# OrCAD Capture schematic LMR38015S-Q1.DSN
size D; title: LMR38015S-Q1: LMR38015 SIMPLE SWITCHER®; rev: 1.0; note: Datasheet: SNVSCH7                  EVM: SNVU847; note: Synchronous Step Down Converter
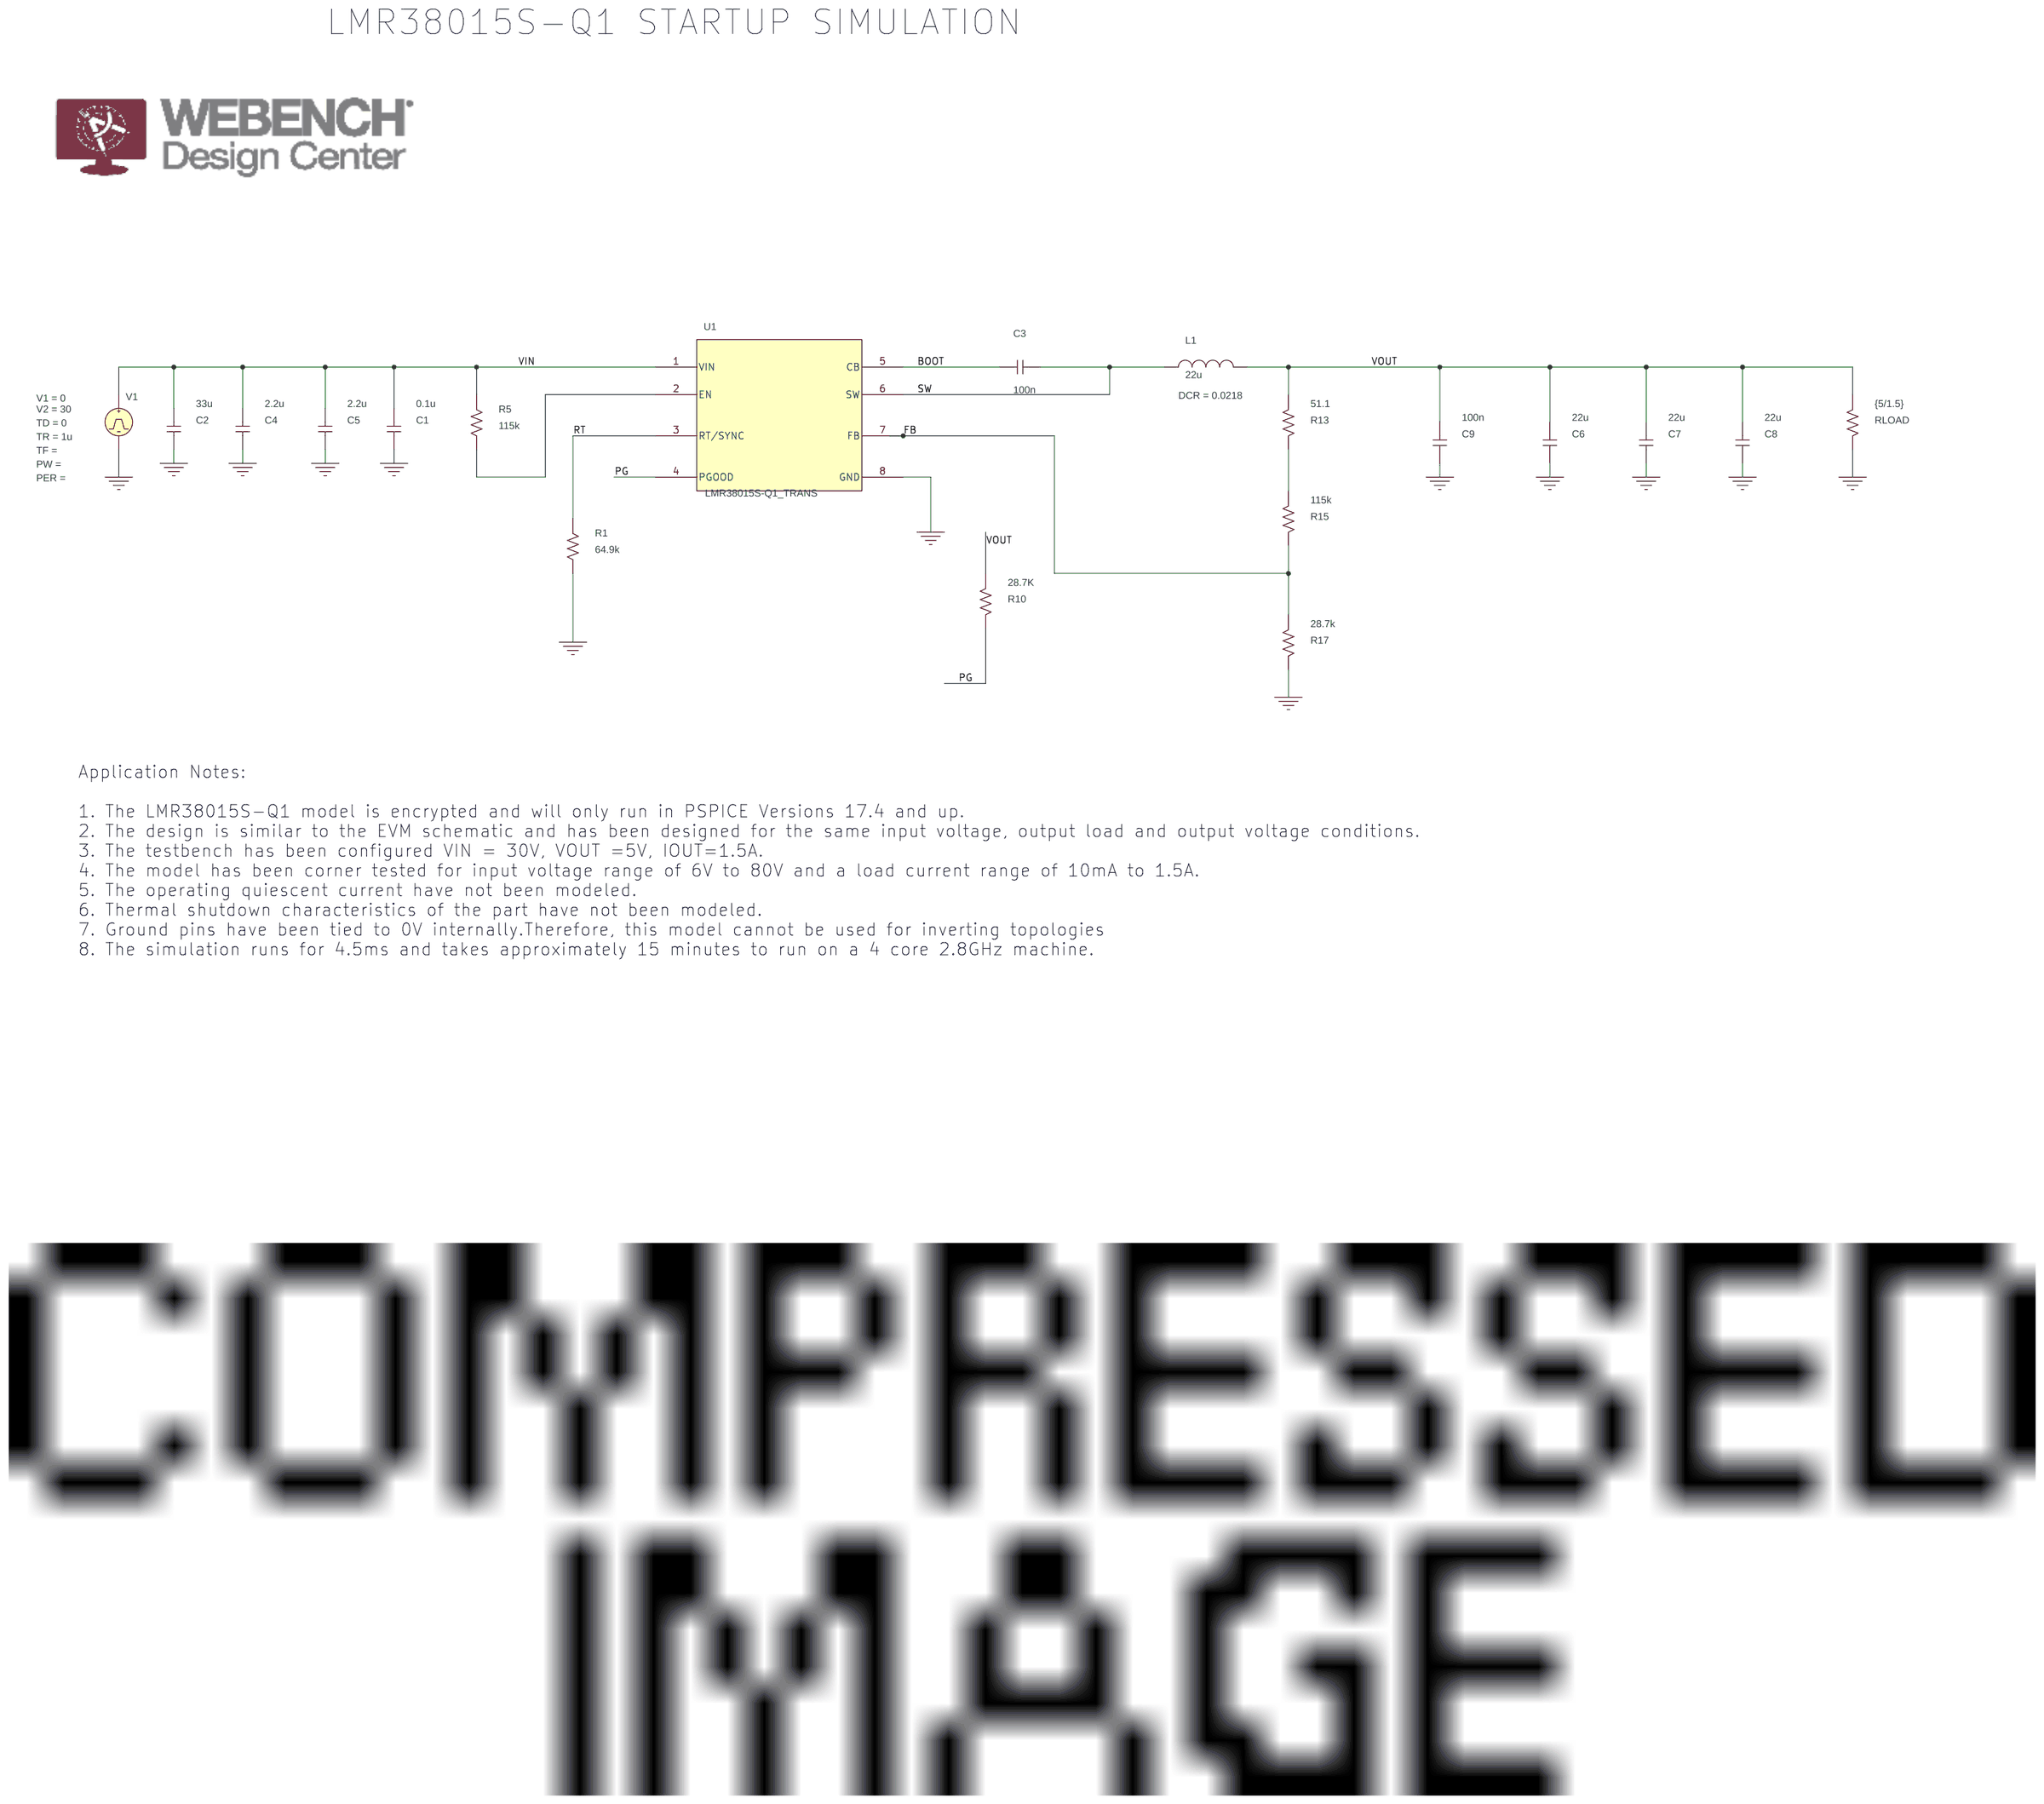
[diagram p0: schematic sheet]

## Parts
C1  0.1u  [RAD/CK05]
C2  33u  [RAD/CK05]
C3  100n  [RAD/CK05]
C4  2.2u  [RAD/CK05]
C5  2.2u  [RAD/CK05]
C6  22u  [RAD/CK05]
C7  22u  [RAD/CK05]
C8  22u  [RAD/CK05]
C9  100n  [RAD/CK05]
L1  22u  [DISC/.350x.175/LS.200x.100/.034]
R1  64.9k  [AX/RC05]
R5  115k  [AX/RC05]
R10  28.7K  [AX/RC05]
R13  51.1  [AX/RC05]
R15  115k  [AX/RC05]
R17  28.7k  [AX/RC05]
RLOAD  {5/1.5}  [AX/RC05]
U1  LMR38015S-Q1_TRANS
V1  VPULSE

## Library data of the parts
C1-C6 C9 = c
C7 C8 = c: IC: 0
L1 = L: DCR: 0.0218; IC: 0
R1 R5 R10 R13 R15 R17 RLOAD = r
U1 = LMR38015S-Q1_TRANS
V1 = VPULSE: TD: 0; TR: 1u; V1: 0; V2: 30

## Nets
VIN: C1.1 C2.1 C4.1 C5.1 R5.1 U1.1(VIN) V1.1(+)
0: C1.2 C2.2 C4.2 C5.2 C6.2 C7.2 C8.2 C9.2 R1.2 R17.2 RLOAD.2 U1.8(GND) V1.2(-)
BOOT: C3.1 U1.5(CB)
FB: R15.2 R17.1 U1.7(FB)
PG: R10.2 U1.4(PGOOD)
RT: R1.1 U1.3(RT/SYNC)
SW: C3.2 L1.1 U1.6(SW)
VOUT: C6.1 C7.1 C8.1 C9.1 L1.2 R10.1 R13.1 RLOAD.1
N16778226: R13.2 R15.1
N16779641: R5.2 U1.2(EN)

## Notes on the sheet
- LMR38015S-Q1 STARTUP SIMULATION
- Application Notes:
  1. The LMR38015S-Q1 model is encrypted and will only run in PSPICE Versions 17.4 and up.
  2. The design is similar to the EVM schematic and has been designed for the same input voltage, output load and output voltage conditions.
  3. The testbench has been configured VIN = 30V, VOUT =5V, IOUT=1.5A.
  4. The model has been corner tested for input voltage range of 6V to 80V and a load current range of 10mA to 1.5A.
  5. The operating quiescent current have not been modeled.
  6. Thermal shutdown characteristics of the part have not been modeled.
  7. Ground pins have been tied to 0V internally.Therefore, this model cannot be used for inverting topologies
  8. The simulation runs for 4.5ms and takes approximately 15 minutes to run on a 4 core 2.8GHz machine.
